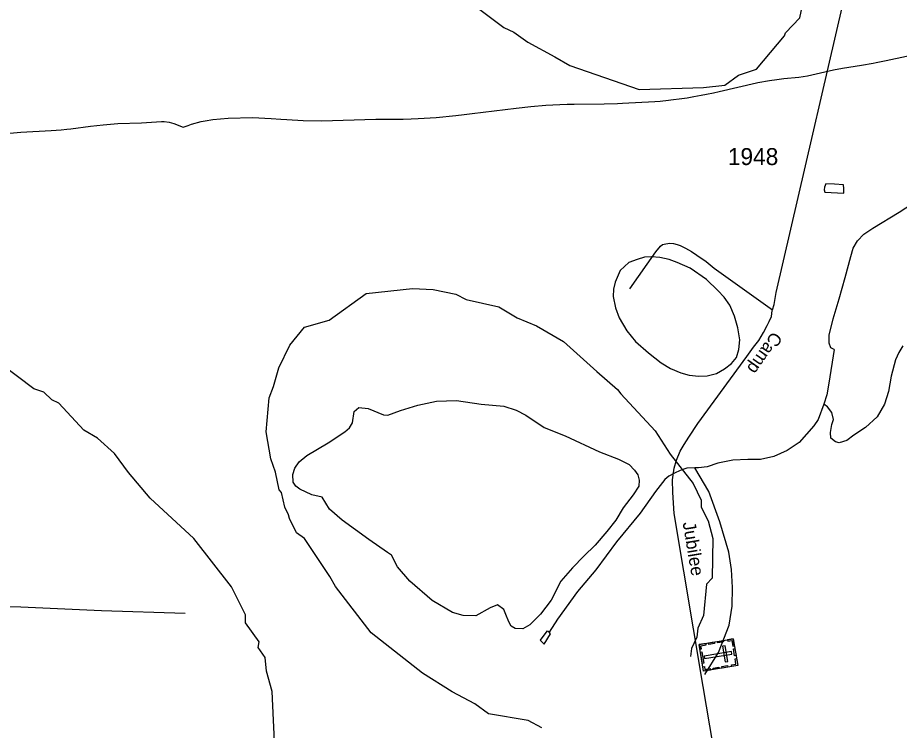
# Model space of a CAD drawing. Extents: x 2206922 to 2357709, y 510027 to 673830.
# Drawn here: x 2317208 to 2323700, y 534674 to 539926 of the extents above; entities that cross this region are included whole.
import ezdxf

# ---------------------------------------------------------------- set-up
doc = ezdxf.new("R2010")
doc.units = 0
for name, color, linetype in [('Exist Cultural Cemetery CELL', 7, 'Continuous'), ('Exist Hydrographic Misc Water Feature', 7, 'Continuous'), ('Exist Hydrographic Pond Under 1500 Sq Ft', 7, 'Continuous'), ('Exist Road Non-System Type 51', 7, 'Continuous'), ('Exist Road Secondary Type 51 Attributed', 7, 'Continuous'), ('Exist Road Secondary Type 51 Label', 7, 'Continuous'), ('Exist Road Secondary Type 51 Number Label', 7, 'Continuous')]:
    doc.layers.add(name, color=color, linetype=linetype)

msp = doc.modelspace()

# ---------------------------------------------------------------- linework, layer by layer
at = {"layer": 'Exist Cultural Cemetery CELL'}
for points in [[(2322477.1, 535348.4), (2322510, 535152.1), (2322258.9, 535110), (2322226, 535306.3)], [(2322434.4, 535341.3), (2322436.2, 535330.1), (2322468, 535335.4), (2322474.7, 535295.4), (2322485.7, 535297.2), (2322477.1, 535348.4)], [(2322231.5, 535273.7), (2322242.8, 535275.6), (2322239.2, 535297.3), (2322279, 535304), (2322277.2, 535315), (2322226, 535306.4)], [(2322294.9, 535317.9), (2322337.7, 535325.1), (2322339.5, 535313.9), (2322296.8, 535306.7)], [(2322361.2, 535329), (2322403.9, 535336.2), (2322405.8, 535325), (2322363.1, 535317.8)], [(2322416.7, 535296.9), (2322398.3, 535293.8), (2322417.7, 535177.7), (2322436.2, 535180.8)], [(2322246.8, 535251.6), (2322260.8, 535167.9), (2322249.6, 535166), (2322235.5, 535249.7)], [(2322466.2, 535236.1), (2322463.1, 535254.5), (2322263.1, 535221), (2322266.2, 535202.6)], [(2322489.3, 535275.4), (2322497.9, 535224.3), (2322486.6, 535222.4), (2322478.1, 535273.5)], [(2322393.3, 535144), (2322436, 535151.2), (2322437.9, 535140), (2322395.2, 535132.8)], [(2322467.2, 535144.8), (2322465.4, 535156), (2322497.1, 535161.4), (2322490.4, 535201.4), (2322501.4, 535203.2), (2322509.9, 535152)], [(2322253.4, 535142.7), (2322264.7, 535144.6), (2322268.3, 535122.9), (2322308.2, 535129.6), (2322310, 535118.6), (2322258.9, 535110)], [(2322328.3, 535133.2), (2322371, 535140.3), (2322372.9, 535129.1), (2322330.1, 535121.9)]]:
    msp.add_lwpolyline(points, close=True, dxfattribs=at)
at = {"layer": 'Exist Hydrographic Misc Water Feature'}
msp.add_line((2322647.3, 539445.8), (2322659, 539447.9), dxfattribs=at)
for points in [[(2323530, 539595.4), (2323603.7, 539609.8), (2323753.6, 539642.4), (2323981.6, 539694.9), (2324090.9, 539717.5)], [(2323530, 539595.4), (2323603.7, 539609.8), (2323753.6, 539642.4), (2323981.6, 539694.9), (2324090.9, 539717.5)], [(2322960.6, 539487.1), (2323024.4, 539497.8), (2323214.5, 539541.3), (2323280.7, 539553.7), (2323420.6, 539575.4), (2323508.5, 539591.2), (2323530, 539595.4)], [(2322960.6, 539487.1), (2323024.4, 539497.8), (2323214.5, 539541.3), (2323280.7, 539553.7), (2323420.6, 539575.4), (2323508.5, 539591.2), (2323530, 539595.4)], [(2322332.3, 539372.9), (2322373.6, 539382), (2322647.3, 539445.8)], [(2322332.3, 539372.9), (2322373.6, 539382), (2322647.3, 539445.8)], [(2322659, 539447.9), (2322743.7, 539463.5), (2322798.4, 539470.6)], [(2322659, 539447.9), (2322743.7, 539463.5), (2322798.4, 539470.6)], [(2322798.4, 539470.6), (2322848.7, 539477.1), (2322960.6, 539487.1)], [(2322798.4, 539470.6), (2322848.7, 539477.1), (2322960.6, 539487.1)], [(2322240.1, 539353.9), (2322280.5, 539361.5), (2322332.3, 539372.9)], [(2322240.1, 539353.9), (2322280.5, 539361.5), (2322332.3, 539372.9)], [(2321626.1, 539293.8), (2321660.6, 539295), (2321899.7, 539308.2)], [(2321626.1, 539293.8), (2321660.6, 539295), (2321899.7, 539308.2)], [(2321899.7, 539308.2), (2321938.6, 539311.5), (2321999.3, 539316.7), (2322018.4, 539319)], [(2322018.4, 539319), (2322098.8, 539328.9), (2322136.9, 539335.3)], [(2322018.4, 539319), (2322098.8, 539328.9), (2322136.9, 539335.3)], [(2322136.9, 539335.3), (2322187.6, 539343.9), (2322240.1, 539353.9)], [(2322136.9, 539335.3), (2322187.6, 539343.9), (2322240.1, 539353.9)], [(2320495.9, 539211.7), (2320555.8, 539218.4), (2320879.7, 539259.7)], [(2320495.9, 539211.7), (2320555.8, 539218.4), (2320879.7, 539259.7)], [(2320879.7, 539259.7), (2320987.4, 539271.4), (2321096.5, 539281), (2321200.7, 539287), (2321254.4, 539288.3)], [(2320879.7, 539259.7), (2320987.4, 539271.4), (2321096.5, 539281), (2321200.7, 539287), (2321254.4, 539288.3)], [(2321254.4, 539288.3), (2321305.6, 539289.4), (2321525.7, 539290.2), (2321626.1, 539293.8)], [(2321254.4, 539288.3), (2321305.6, 539289.4), (2321525.7, 539290.2), (2321626.1, 539293.8)], [(2318588.5, 539164.7), (2318646.5, 539175.3), (2318759.5, 539184.9), (2318938.5, 539188.9)], [(2318588.5, 539164.7), (2318646.5, 539175.3), (2318759.5, 539184.9), (2318938.5, 539188.9)], [(2318938.5, 539188.9), (2319074.5, 539183.3), (2319145, 539177.7)], [(2318938.5, 539188.9), (2319074.5, 539183.3), (2319145, 539177.7)], [(2319145, 539177.7), (2319190.5, 539174.1), (2319311.5, 539166.9), (2319445.6, 539165.7), (2319844.6, 539176.8)], [(2319145, 539177.7), (2319190.5, 539174.1), (2319311.5, 539166.9), (2319445.6, 539165.7), (2319844.6, 539176.8)], [(2319844.6, 539176.8), (2319850.4, 539177), (2319886.7, 539177.2)], [(2319886.7, 539177.2), (2320047.6, 539178.7), (2320106.1, 539180.5)], [(2319886.7, 539177.2), (2320047.6, 539178.7), (2320106.1, 539180.5)], [(2320106.1, 539180.5), (2320157.4, 539182.2), (2320290.6, 539191), (2320435.6, 539204.7), (2320495.9, 539211.7)], [(2320106.1, 539180.5), (2320157.4, 539182.2), (2320290.6, 539191), (2320435.6, 539204.7), (2320495.9, 539211.7)], [(2317571.2, 539103.7), (2317599.5, 539106.8), (2317744.5, 539126.9)], [(2317571.2, 539103.7), (2317599.5, 539106.8), (2317744.5, 539126.9)], [(2317744.5, 539126.9), (2317837.6, 539136.9), (2317946.5, 539144.9), (2318119.7, 539151.1), (2318266.6, 539161.4)], [(2317744.5, 539126.9), (2317837.6, 539136.9), (2317946.5, 539144.9), (2318119.7, 539151.1), (2318266.6, 539161.4)], [(2318266.6, 539161.4), (2318287.5, 539160.8), (2318323.6, 539155.7)], [(2318266.6, 539161.4), (2318287.5, 539160.8), (2318323.6, 539155.7)], [(2318323.6, 539155.7), (2318358.6, 539146), (2318427.5, 539119), (2318462.8, 539131)], [(2318323.6, 539155.7), (2318358.6, 539146), (2318427.5, 539119), (2318462.8, 539131)], [(2318462.8, 539131), (2318489.5, 539140.2), (2318559.8, 539159.5), (2318588.5, 539164.7)], [(2318462.8, 539131), (2318489.5, 539140.2), (2318559.8, 539159.5), (2318588.5, 539164.7)], [(2316940.9, 539061.4), (2316987.5, 539062.9), (2317067.4, 539068.2), (2317231.5, 539082.9), (2317455.6, 539093.9), (2317529.4, 539098.9), (2317571.2, 539103.7)], [(2316940.9, 539061.4), (2316987.5, 539062.9), (2317067.4, 539068.2), (2317231.5, 539082.9), (2317455.6, 539093.9), (2317529.4, 539098.9), (2317571.2, 539103.7)], [(2323223.9, 538698.9), (2323157.9, 538702.2), (2323150.1, 538676.1), (2323146.4, 538656.1), (2323150.7, 538640.1), (2323290.5, 538633.6), (2323290.3, 538665.7), (2323289.9, 538693.6), (2323223.9, 538698.9)], [(2323219.2, 537479.5), (2323196.8, 537493.2), (2323184.5, 537527.1), (2323183.9, 537585), (2323212.6, 537705.3), (2323257.1, 537853.7), (2323301.4, 538012.1), (2323343.7, 538166.5), (2323360.9, 538226.7), (2323392.5, 538280.9), (2323439.8, 538329.4), (2323505.4, 538374.1), (2323697.8, 538492.1), (2323852.6, 538593.7)], [(2321645.6, 538062.2), (2321606.7, 537977.8), (2321595.2, 537925.7), (2321593.7, 537871.8), (2321610.6, 537788), (2321637.4, 537714.3), (2321694.4, 537618.9), (2321757.2, 537539.7), (2321852.1, 537454.7), (2321946.8, 537381.8), (2322015.1, 537340.6), (2322091.6, 537309.5), (2322153.5, 537292.1), (2322223.9, 537282.9), (2322285.6, 537287.5), (2322353.3, 537304.2), (2322413.1, 537336.9), (2322464.6, 537377.4), (2322502.1, 537421.8), (2322519.3, 537480), (2322526.5, 537552), (2322511.8, 537639.7), (2322486.9, 537725.5), (2322451.9, 537807.1), (2322409.4, 537866.6), (2322364.9, 537916.1), (2322280.1, 537995.1), (2322161.1, 538079.8), (2322064.7, 538122.7), (2322004.7, 538144), (2321936.4, 538159.3), (2321874.3, 538162.6), (2321822.6, 538160.1), (2321768.7, 538143.5), (2321709.2, 538120.9), (2321645.6, 538062.2)], [(2323726.7, 537506.9), (2323697.2, 537458.6), (2323671.5, 537404.4), (2323640.8, 537284.1), (2323620.1, 537171.9), (2323591.2, 537077.7), (2323536.4, 536983.2), (2323451.1, 536906.3), (2323365.8, 536849.4), (2323312.3, 536810.8), (2323256.3, 536792.3), (2323230.5, 536800), (2323196.2, 536827.5), (2323193.6, 536869.6), (2323203.2, 536927.6), (2323216.5, 536963.7), (2323204.2, 537015.6), (2323171.6, 537057.2), (2323145.4, 537076.9)], [(2323219.2, 537479.5), (2323181.9, 537233.2), (2323166.7, 537147.1), (2323145.4, 537076.9)], [(2319104.6, 534485), (2319082.5, 534960), (2319039.6, 535109.2), (2319030.6, 535210.5), (2318979.5, 535284), (2318987.5, 535327), (2318885.6, 535467.2), (2318885.6, 535526.3), (2318782.5, 535732.1), (2318504.6, 536088.5), (2318184.5, 536384.1), (2318024.6, 536574.5), (2317922.5, 536714.8), (2317796.6, 536827.9), (2317696.5, 536886.1), (2317510.5, 537085.4), (2317460.5, 537109.6), (2317401.5, 537166.3), (2317326.4, 537189.6), (2317074.6, 537379.6)], [(2321376.6, 535956.4), (2321293.3, 535871.5), (2321208.7, 535772.7), (2321136.1, 535634), (2321057.3, 535531.2), (2320980, 535452.4), (2320928.6, 535421.8), (2320872.6, 535425.3), (2320842.4, 535440.9), (2320824.2, 535472.7), (2320803.3, 535526.5), (2320789.1, 535564.3), (2320740.5, 535597.8), (2320686.8, 535577.2), (2320581.6, 535518.1), (2320489.5, 535521.1), (2320409.6, 535542.2), (2320260.5, 535630.5), (2320095, 535772.7), (2320006, 535877.7), (2319961.1, 535965.2), (2319930.8, 535984.9), (2319794, 536081.3), (2319596.5, 536223.1), (2319503.9, 536304), (2319450.7, 536391.4), (2319374.5, 536410.6), (2319286.3, 536451.6), (2319256.1, 536473.3), (2319235.8, 536503), (2319235, 536559.1), (2319248.6, 536607.1), (2319282, 536651.5), (2319337.6, 536700), (2319494.6, 536791.7), (2319617.4, 536873), (2319651.1, 536903.3), (2319674.9, 536939.5), (2319685.7, 537023.6), (2319719.6, 537052), (2319789.5, 537046.7), (2319902.1, 536998), (2319934, 536996.3), (2320027.6, 537031.3), (2320155.1, 537070.7), (2320292.9, 537100.1), (2320440.5, 537105.7), (2320620.8, 537077.7), (2320788.9, 537063.5), (2320879.1, 537034.5), (2320949.7, 536997.3), (2321084.4, 536906.7), (2321239, 536844.5), (2321492, 536725.3), (2321632.5, 536672.8), (2321711, 536633.7), (2321749.4, 536590.1), (2321775.8, 536556.4), (2321784, 536518.6), (2321782.6, 536474.5), (2321739.3, 536410.1), (2321666.5, 536313.4), (2321611.6, 536222.8), (2321546.4, 536138.1), (2321459.6, 536037.3), (2321376.6, 535956.4)], [(2323145.4, 537076.9), (2323102.7, 536964.5), (2323071.1, 536918.2), (2322962.7, 536795), (2322875.3, 536736.2), (2322775.9, 536693.1), (2322678.1, 536670.1), (2322584.1, 536671), (2322474.4, 536665.9), (2322362.7, 536642.7), (2322284.8, 536615.9), (2322221.2, 536609.2), (2322195.2, 536608.9)], [(2322195.2, 536608.9), (2322135.1, 536606.2), (2322087.3, 536589.7), (2322043.6, 536569.3), (2322003.8, 536546.9), (2321974.1, 536522.6), (2321905, 536433.9), (2321790.8, 536274.7), (2321617.1, 536063), (2321465.6, 535857.4), (2321331.3, 535696.1), (2321183.6, 535492.6), (2321120.7, 535398)], [(2322267.3, 535084.4), (2322367.6, 535247.5), (2322447.4, 535450.2), (2322469.9, 535588.4), (2322472.4, 535726.4), (2322464.8, 535860.2), (2322445.5, 535985.9), (2322379.1, 536211.1), (2322296.9, 536434.1), (2322195.2, 536608.9)], [(2316072.7, 535633.4), (2316552.7, 535602.6), (2317232.7, 535584), (2317826.7, 535556.4), (2318440.5, 535537)], [(2321120.7, 535398), (2321114.5, 535401.9), (2321104.5, 535405.8), (2321055.3, 535337.3), (2321085.6, 535309.6), (2321130.9, 535386.1), (2321120.7, 535398)]]:
    msp.add_lwpolyline(points, dxfattribs=at)
at = {"layer": 'Exist Hydrographic Pond Under 1500 Sq Ft'}
for points in [[(2320484.6, 540083.2), (2320787.5, 539852.6), (2320862.5, 539819.6), (2320963.6, 539744.9), (2321164.6, 539638.1), (2321273.7, 539573.6), (2321783.6, 539397.2), (2322258.5, 539409.9), (2322415.6, 539429.3), (2322515.7, 539502.2), (2322647.5, 539547), (2322853.6, 539791.6), (2322861.6, 539814.8), (2322968.6, 539924.2), (2323008.6, 540125.9)], [(2321067.6, 534692.1), (2320967.5, 534747.1), (2320675.5, 534794.4), (2320574.6, 534869.1), (2320407.5, 534957.6), (2320188.5, 535096.5), (2319810.6, 535393), (2319549.6, 535733.5), (2319506.5, 535807.3), (2319320.5, 536088.6), (2319261.5, 536128.9), (2319210.6, 536235.1), (2319201.6, 536261), (2319176.6, 536319.1), (2319150.5, 536426.3), (2319133.5, 536445.3), (2319106.5, 536575.5), (2319072.6, 536675.8), (2319037.6, 536874.5), (2319059.5, 537124.9), (2319091.5, 537208.3), (2319131.5, 537344.4), (2319213.5, 537511.7), (2319320.5, 537644), (2319502.6, 537697.3), (2319775.5, 537892.1), (2320116.5, 537928.8), (2320266.6, 537921.7), (2320433.6, 537889.1), (2320509.6, 537849.5), (2320751.6, 537793.6), (2320885.5, 537713.7), (2321027.6, 537653.8), (2321228.5, 537540.5), (2321472.6, 537317.3), (2321624.5, 537185.6), (2321649.5, 537153.8), (2321902.5, 536881.8), (2322012.7, 536709), (2322181.6, 536492.7), (2322240.7, 536370.4), (2322241.7, 536317.9), (2322292.6, 536218.2), (2322327.6, 536088.4), (2322321.7, 535796.1), (2322280.7, 535751.8), (2322258.5, 535521.1), (2322217.5, 535427.6), (2322209.5, 535361.7), (2322169.5, 535278), (2322161.5, 535218.6)]]:
    msp.add_lwpolyline(points, dxfattribs=at)
at = {"layer": 'Exist Road Non-System Type 51'}
msp.add_lwpolyline([(2321715.1, 537926.7), (2321908.1, 538200.7), (2321941.6, 538243), (2321955.5, 538255), (2321981.4, 538259.4), (2322009.4, 538263.6), (2322037.5, 538261.9), (2322065.4, 538254.2), (2322087.5, 538246.5), (2322125.7, 538226.9), (2322170, 538201.4), (2322208.2, 538175.8), (2322276.7, 538128.7), (2322337.3, 538079.4), (2322766.4, 537772.2)], dxfattribs=at)
at = {"layer": 'Exist Road Secondary Type 51 Attributed'}
msp.add_lwpolyline([(2322329, 534561.1), (2322256.4, 534998.1), (2322042.8, 536273.1), (2322031.2, 536426.9), (2322030.2, 536520.9), (2322043.2, 536605), (2322058.6, 536665), (2322086, 536731.3), (2322115.3, 536781.5), (2322150.6, 536834), (2322217.6, 536934.7), (2322576.2, 537428.2), (2322625.3, 537496.6), (2322664.8, 537547), (2322700.1, 537605.5), (2322727.6, 537657.8), (2322741.2, 537687.9), (2322758.9, 537724.1), (2322764.4, 537768.1), (2322766.4, 537772.2), (2322777.8, 537812.2), (2322792.8, 537900.3), (2323394.6, 540502.5)], dxfattribs=at)

# ---------------------------------------------------------------- texts
at = {"layer": 'Exist Road Secondary Type 51 Label'}
for s, rotation, p in [('Camp', 235.0578, (2322768.1, 537618.6)), ('Jubilee', 279.51037, (2322104.4, 536203.2))]:
    msp.add_text(s, height=95, rotation=rotation, dxfattribs=at).set_placement(p)
at = {"layer": 'Exist Road Secondary Type 51 Number Label'}
msp.add_text('1948', height=125, dxfattribs=at).set_placement((2322437.2, 538839.6))

doc.saveas('drawing.dxf')
